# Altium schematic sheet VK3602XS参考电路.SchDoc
size A4
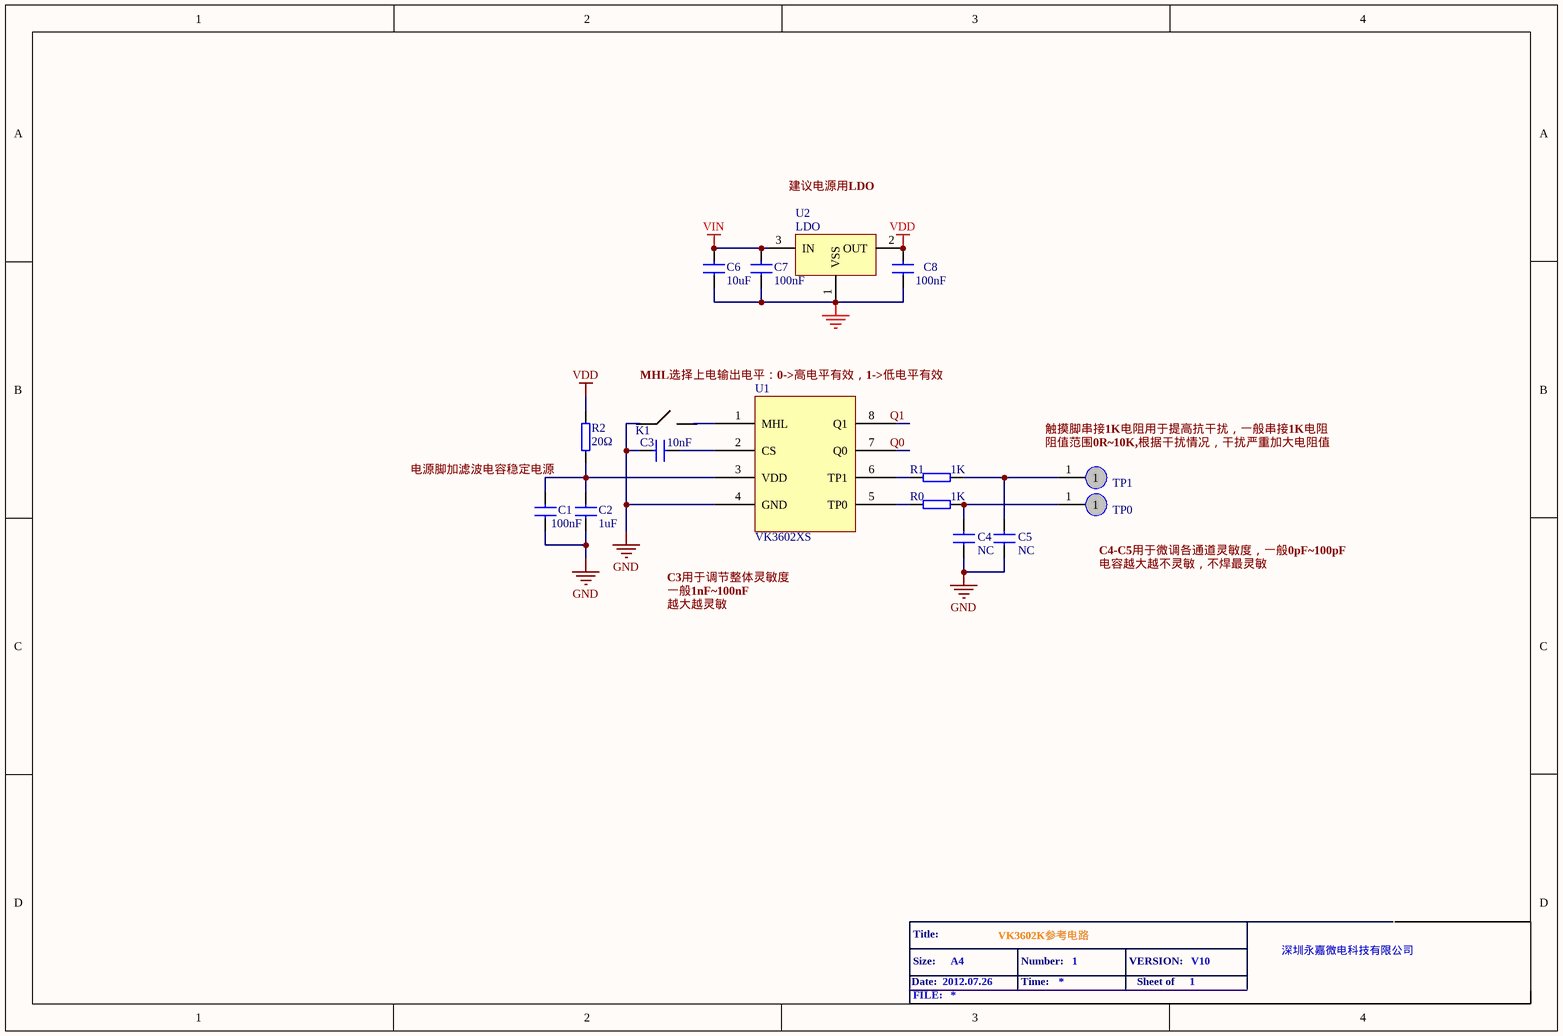
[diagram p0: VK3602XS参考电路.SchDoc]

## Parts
C1  100nF  [0603-C]
C2  value 1uF  [0603-C]  (hidden comment: 10uF)
C3  value 10nF  [0603-C]  (hidden comment: 10uF)
C4  value NC  [0603-C]  (hidden comment: 10uF)
C5  value NC  [0603-C]  (hidden comment: 10uF)
C6  10uF  [0805-C]
C7  100nF  [0805-C]
C8  100nF  [0805-C]
K1  单刀单掷开关  (value not drawn)
R0  1K  [0603-R]
R1  1K  [0603-R]
R2  20Ω  [0603-R]
TP0  TPAD  [TP-PAD0]  (value not drawn)
TP1  TPAD  [TP-PAD0]  (value not drawn)
U1  VK3602XS
U2  LDO  [SOT-23]

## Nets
GND: C1.2 C2.2 C3.1 C4.1 C5.1 C6.2 C7.2 C8.2 U1.4(GND) U2.1(VSS)
VDD: C8.1 R2.1 U2.2(OUT)
VIN: C6.1 C7.1 U2.3(IN)
NetC1_1: C1.1 C2.1 R2.2 U1.3(VDD)
NetC3_2: C3.2 U1.2(CS)
NetC4_2: C4.2 R0.1 TP0.1
NetC5_2: C5.2 R1.1 TP1.1
NetR0_2: R0.2 U1.5(TP0)
NetR1_2: R1.2 U1.6(TP1)

Not connected (* = marked no-connect by the designer): U1 1(MHL) 7(Q0) 8(Q1)

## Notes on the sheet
- 建议电源用LDO
- MHL选择上电输出电平：0->高电平有效，1->低电平有效
- (near TP1) 触摸脚串接1K电阻用于提高抗干扰，一般串接1K电阻
- (near TP1) 阻值范围0R
  0K,根据干扰情况，干扰严重加大电阻值
- 电源脚加滤波电容稳定电源
- C3用于调节整体灵敏度
- (near TP0) C4-C5用于微调各通道灵敏度，一般0pF
  00pF
- 电容越大越不灵敏，不焊最灵敏
- 一般1nF
  00nF
- 越大越灵敏
- Date:
- Title:
- Size:
- 2012.07.26
- A4
- VK3602K参考电路
- Number:
- Time:
- 1
- VERSION:
- Sheet of
- V10
- 深圳永嘉微电科技有限公司
- FILE:
- Labels drawn without touching a wire or pin: Q0, Q1

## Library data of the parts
C1-C8 = CAP: Capacitor
R0-R2 = RES: Resistor
TP0 TP1 = TPAD: TESTING
U2 = V6206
